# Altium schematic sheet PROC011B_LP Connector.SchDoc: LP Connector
size 431 x 279 mm; Date: Not shown in title block; ApprovedBy: Not shown in title block; CheckedBy: Not shown in title block; Author: Not shown in title block; CompanyName: Not shown in title block; Engineer: Not shown in title block; Organization: Not shown in title block; Address1: Not shown in title block; Address2: Not shown in title block; Address3: Not shown in title block; Address4: Not shown in title block; DocumentNumber: 1; Revision: Use project parameter SCH_Rev; SheetNumber: 10; SheetTotal: 17; PageSetup: Record=PageOptions¦CenterHorizontal=True¦CenterVertical=True¦PrintScale=1.00¦XCorrection=1.00¦YCorrection=1.00¦PrintKind=0¦BorderSize=5000000¦LeftOffset=0¦BottomOffset=0¦Orientation=2¦PaperLength=1000¦PaperWidth=1000¦Scale=100¦PaperSource=15¦PrintQuality=600¦MediaType=1¦DitherType=10¦PaperKind=Letter¦PrintScaleMode=1
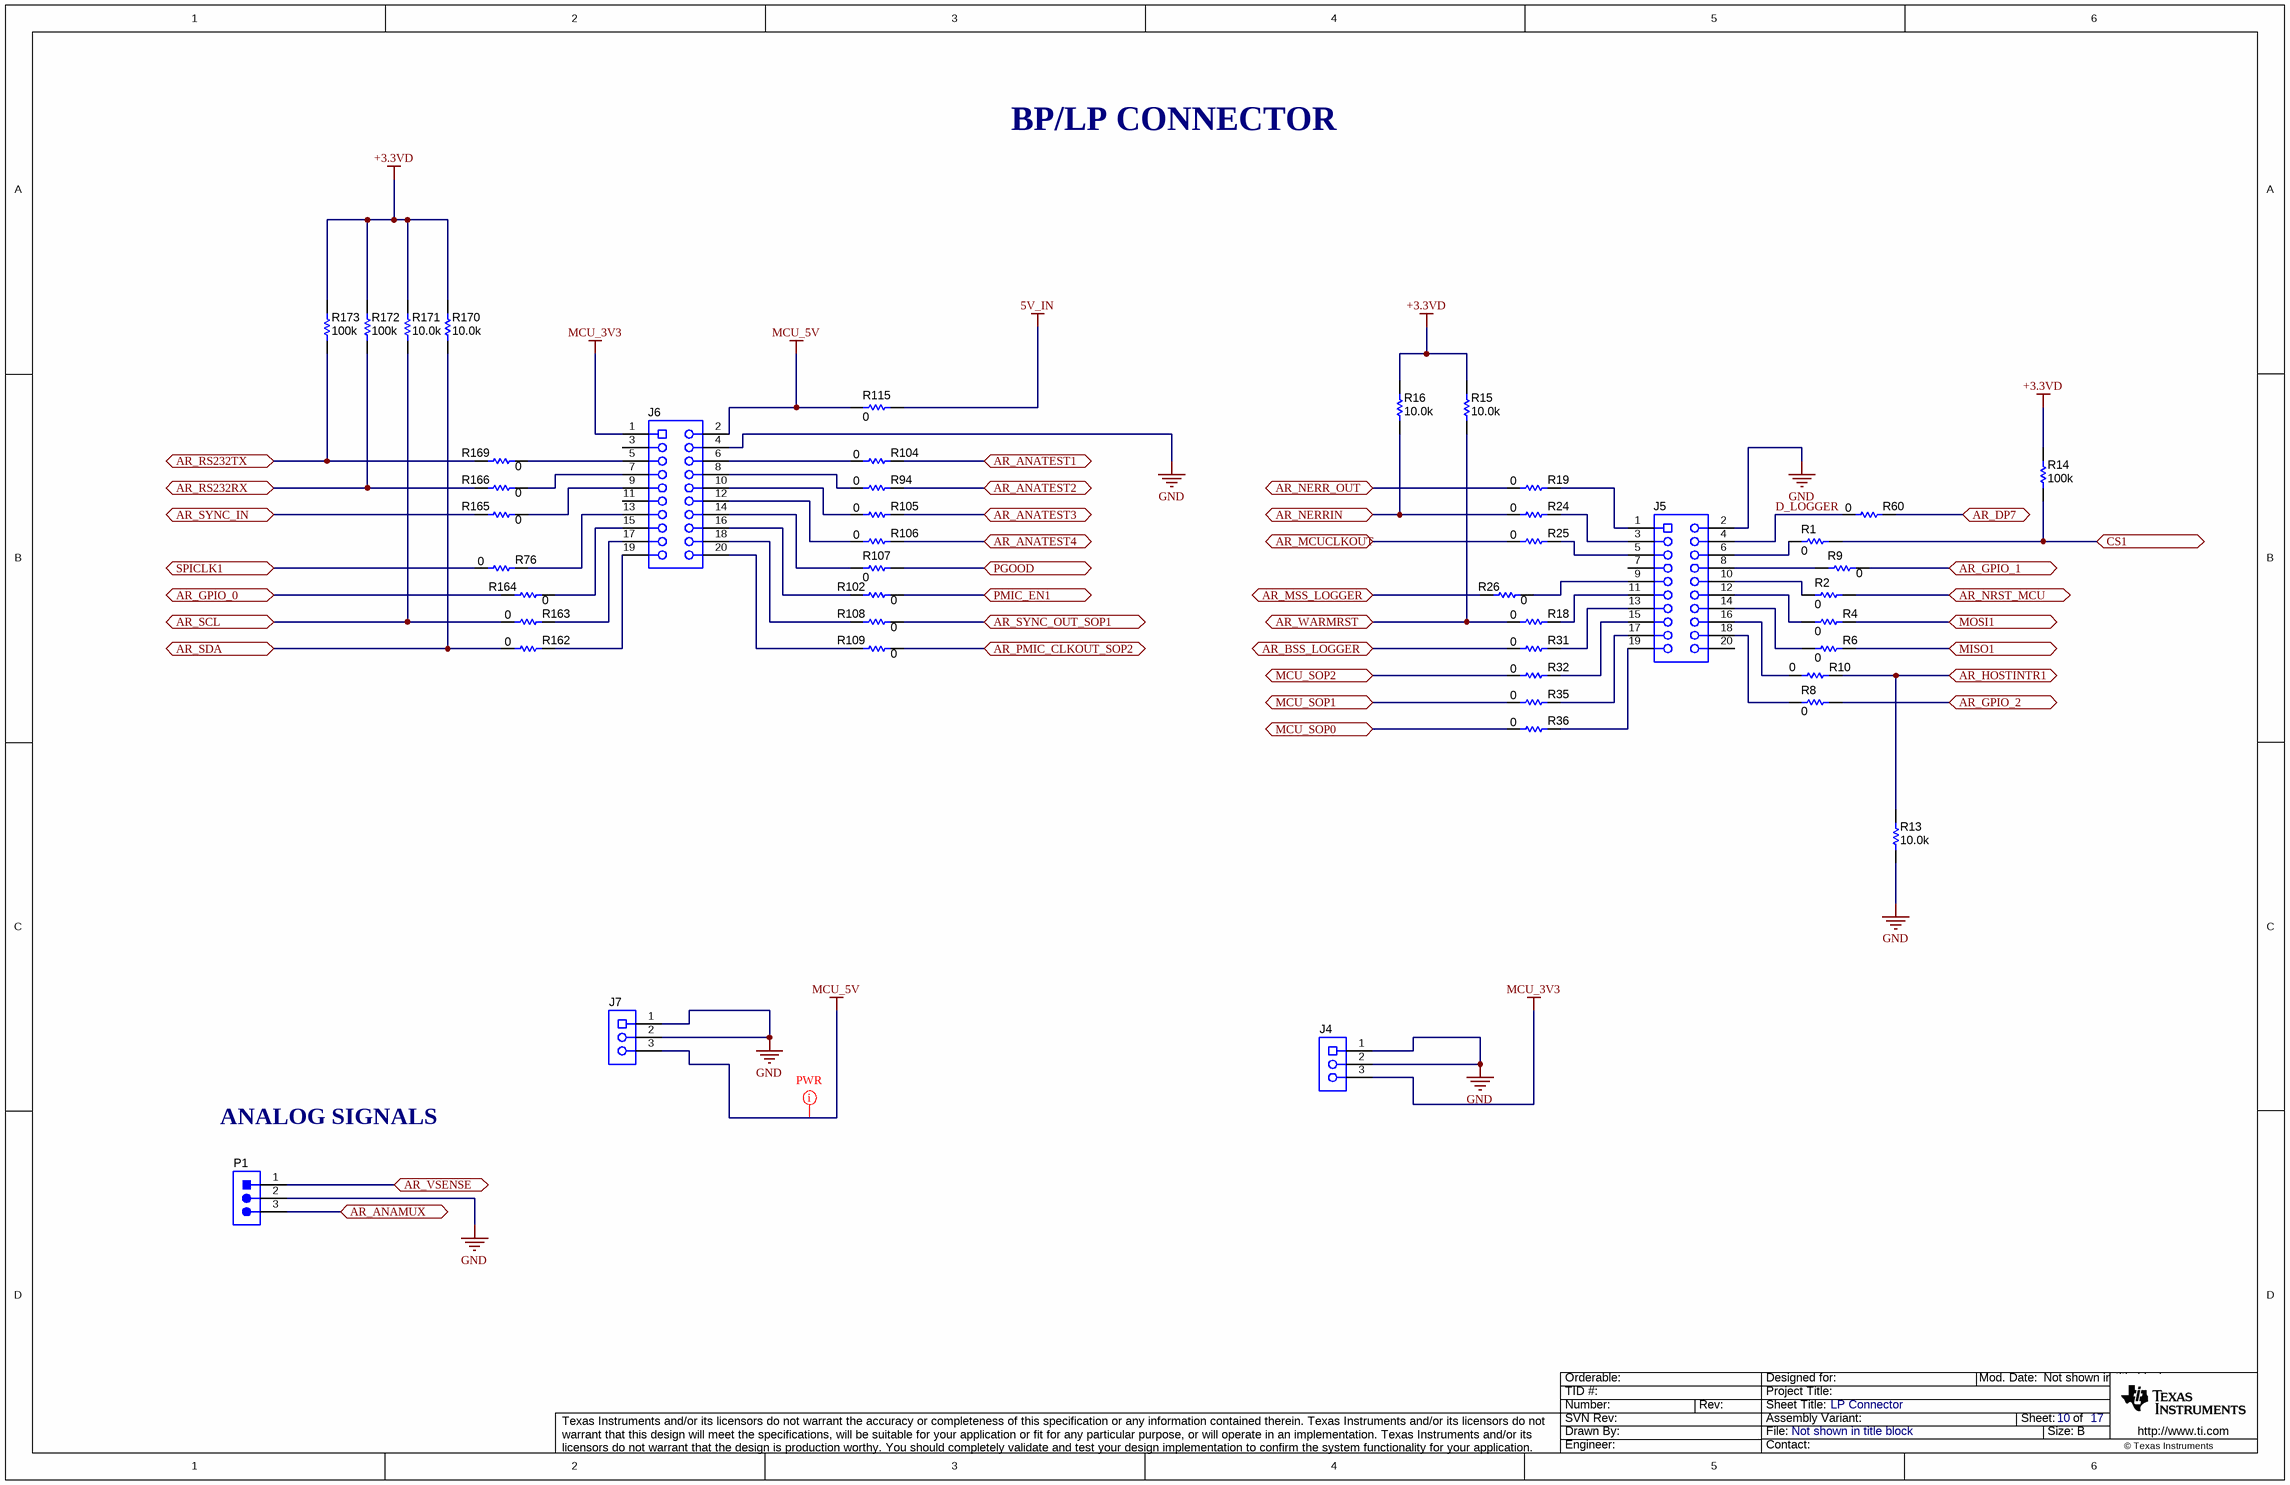
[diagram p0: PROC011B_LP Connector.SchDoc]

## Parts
J4  SSM-103-S-SV  [Samtec_SSM-103-x-SV]  (value not drawn)
J5  SSM-110-S-DV  [Samtec_SSM-110-x-DV]  (value not drawn)
J6  SSM-110-S-DV  [Samtec_SSM-110-x-DV]  (value not drawn)
J7  SSM-103-S-SV  [Samtec_SSM-103-x-SV]  (value not drawn)
P1  TSW-103-07-T-S  [Samtec_TSW-103-07-T-S]  (value not drawn)
R1  ValueDisplayed: 0  [0201_Silk]  (hidden comment: CRCW02010000Z0ED)
R2  ValueDisplayed: 0  [0201_Silk]  (hidden comment: CRCW02010000Z0ED)
R4  ValueDisplayed: 0  [0201_Silk]  (hidden comment: CRCW02010000Z0ED)
R6  ValueDisplayed: 0  [0201_Silk]  (hidden comment: CRCW02010000Z0ED)
R8  ValueDisplayed: 0  [0201_Silk]  (hidden comment: CRCW02010000Z0ED)
R9  ValueDisplayed: 0  [0201_Silk]  (hidden comment: CRCW02010000Z0ED)
R10  ValueDisplayed: 0  [0201_Silk]  (hidden comment: CRCW02010000Z0ED)
R13  ValueDisplayed: 10.0k  [0402L]  (hidden comment: CRCW040210K0FKED)
R14  ValueDisplayed: 100k  [0402L]  (hidden comment: CRCW0402100KFKED)
R15  ValueDisplayed: 10.0k  [0402L]  (hidden comment: CRCW040210K0FKED)
R16  ValueDisplayed: 10.0k  [0402L]  (hidden comment: CRCW040210K0FKED)
R18  ValueDisplayed: 0  [0201_Silk]  (hidden comment: CRCW02010000Z0ED)
R19  ValueDisplayed: 0  [0201_Silk]  (hidden comment: CRCW02010000Z0ED)
R24  ValueDisplayed: 0  [0201_Silk]  (hidden comment: CRCW02010000Z0ED)
R25  ValueDisplayed: 0  [0201_Silk]  (hidden comment: CRCW02010000Z0ED)
R26  ValueDisplayed: 0  [0201_Silk]  (hidden comment: CRCW02010000Z0ED)
R31  ValueDisplayed: 0  [0201_Silk]  (hidden comment: CRCW02010000Z0ED)
R32  ValueDisplayed: 0  [0201_Silk]  (hidden comment: CRCW02010000Z0ED)
R35  ValueDisplayed: 0  [0201_Silk]  (hidden comment: CRCW02010000Z0ED)
R36  ValueDisplayed: 0  [0201_Silk]  (hidden comment: CRCW02010000Z0ED)
R60  ValueDisplayed: 0  [0201_Silk]  (hidden comment: CRCW02010000Z0ED)
R76  ValueDisplayed: 0  [0201_Silk]  (hidden comment: CRCW02010000Z0ED)
R94  ValueDisplayed: 0  [0201_Silk]  (hidden comment: CRCW02010000Z0ED)
R102  ValueDisplayed: 0  [0201_Silk]  (hidden comment: CRCW02010000Z0ED)
R104  ValueDisplayed: 0  [0201_Silk]  (hidden comment: CRCW02010000Z0ED)
R105  ValueDisplayed: 0  [0201_Silk]  (hidden comment: CRCW02010000Z0ED)
R106  ValueDisplayed: 0  [0201_Silk]  (hidden comment: CRCW02010000Z0ED)
R107  ValueDisplayed: 0  [0402L]  (hidden comment: ERJ-2GE0R00X)
R108  ValueDisplayed: 0  [0201_Silk]  (hidden comment: CRCW02010000Z0ED)
R109  ValueDisplayed: 0  [0201_Silk]  (hidden comment: CRCW02010000Z0ED)
R115  ValueDisplayed: 0  [2010]  (hidden comment: CRCW20100000Z0EF)
R162  ValueDisplayed: 0  [0201_Silk]  (hidden comment: CRCW02010000Z0ED)
R163  ValueDisplayed: 0  [0201_Silk]  (hidden comment: CRCW02010000Z0ED)
R164  ValueDisplayed: 0  [0201_Silk]  (hidden comment: CRCW02010000Z0ED)
R165  ValueDisplayed: 0  [0201_Silk]  (hidden comment: CRCW02010000Z0ED)
R166  ValueDisplayed: 0  [0201_Silk]  (hidden comment: CRCW02010000Z0ED)
R169  ValueDisplayed: 0  [0201_Silk]  (hidden comment: CRCW02010000Z0ED)
R170  ValueDisplayed: 10.0k  [0402L]  (hidden comment: CRCW040210K0FKED)
R171  ValueDisplayed: 10.0k  [0402L]  (hidden comment: CRCW040210K0FKED)
R172  ValueDisplayed: 100k  [0402L]  (hidden comment: CRCW0402100KFKED)
R173  ValueDisplayed: 100k  [0402L]  (hidden comment: CRCW0402100KFKED)

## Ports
AR_ANAMUX, AR_ANATEST1, AR_ANATEST2, AR_ANATEST3, AR_ANATEST4, AR_BSS_LOGGER, AR_DP7, AR_GPIO_0, AR_GPIO_1, AR_GPIO_2, AR_HOSTINTR1, AR_MCUCLKOUT, AR_MSS_LOGGER, AR_NERR_OUT, AR_NERRIN, AR_NRST_MCU, AR_PMIC_CLKOUT_SOP2, AR_RS232RX, AR_RS232TX, AR_SCL, AR_SDA, AR_SYNC_IN, AR_SYNC_OUT_SOP1, AR_VSENSE, AR_WARMRST, CS1, MCU_SOP0, MCU_SOP1, MCU_SOP2, MISO1, MOSI1, PGOOD, PMIC_EN1, SPICLK1

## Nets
5V_IN: R115.2
+3.3VD: R14.2 R15.2 R16.2 R170.2 R171.2 R172.2 R173.2
GND: J4.1 J4.2 J5.2 J6.4 J7.1 J7.2 P1.2 R13.1
MCU_3V3: J4.3 J6.1
MCU_5V: J6.2 J7.3 R115.1
AR_ANAMUX: P1.3 ; port AR_ANAMUX
AR_ANATEST1: R104.2 ; port AR_ANATEST1
AR_ANATEST2: R94.2 ; port AR_ANATEST2
AR_ANATEST3: R105.2 ; port AR_ANATEST3
AR_ANATEST4: R106.2 ; port AR_ANATEST4
AR_BSS_LOGGER: R31.1 ; port AR_BSS_LOGGER
AR_DP7: R60.2 ; port AR_DP7
AR_GPIO_0: R164.1 ; port AR_GPIO_0
AR_GPIO_1: R9.2 ; port AR_GPIO_1
AR_GPIO_2: R8.2 ; port AR_GPIO_2
AR_HOSTINTR1: R10.2 R13.2 ; port AR_HOSTINTR1
AR_MCUCLKOUT: R25.1 ; port AR_MCUCLKOUT
AR_MSS_LOGGER: R26.1 ; port AR_MSS_LOGGER
AR_NERR_OUT: R19.1 ; port AR_NERR_OUT
AR_NERRIN: R16.1 R24.1 ; port AR_NERRIN
AR_NRST_MCU: R2.2 ; port AR_NRST_MCU
AR_PMIC_CLKOUT_SOP2: R109.2 ; port AR_PMIC_CLKOUT_SOP2
AR_RS232RX: R166.1 R172.1 ; port AR_RS232RX
AR_RS232TX: R169.1 R173.1 ; port AR_RS232TX
AR_SCL: R163.1 R171.1 ; port AR_SCL
AR_SDA: R162.1 R170.1 ; port AR_SDA
AR_SYNC_IN: R165.1 ; port AR_SYNC_IN
AR_SYNC_OUT_SOP1: R108.2 ; port AR_SYNC_OUT_SOP1
AR_VSENSE: P1.1 ; port AR_VSENSE
AR_WARMRST: R15.1 R18.1 ; port AR_WARMRST
CS1: R1.2 R14.1 ; port CS1
D_LOGGER: J5.4 R60.1
MCU_SOP0: R36.1 ; port MCU_SOP0
MCU_SOP1: R35.1 ; port MCU_SOP1
MCU_SOP2: R32.1 ; port MCU_SOP2
MISO1: R6.2 ; port MISO1
MOSI1: R4.2 ; port MOSI1
PGOOD: R107.2 ; port PGOOD
PMIC_EN1: R102.2 ; port PMIC_EN1
SPICLK1: R76.1 ; port SPICLK1
NetJ5_1: J5.1 R19.2
NetJ5_3: J5.3 R24.2
NetJ5_5: J5.5 R25.2
NetJ5_6: J5.6 R1.1
NetJ5_8: J5.8 R9.1
NetJ5_9: J5.9 R26.2
NetJ5_10: J5.10 R2.1
NetJ5_11: J5.11 R18.2
NetJ5_12: J5.12 R4.1
NetJ5_13: J5.13 R31.2
NetJ5_14: J5.14 R6.1
NetJ5_15: J5.15 R32.2
NetJ5_16: J5.16 R10.1
NetJ5_17: J5.17 R35.2
NetJ5_18: J5.18 R8.1
NetJ5_19: J5.19 R36.2
NetJ6_5: J6.5 R169.2
NetJ6_6: J6.6 R104.1
NetJ6_7: J6.7 R166.2
NetJ6_8: J6.8 R94.1
NetJ6_9: J6.9 R165.2
NetJ6_10: J6.10 R105.1
NetJ6_12: J6.12 R106.1
NetJ6_13: J6.13 R76.2
NetJ6_14: J6.14 R107.1
NetJ6_15: J6.15 R164.2
NetJ6_16: J6.16 R102.1
NetJ6_17: J6.17 R163.2
NetJ6_18: J6.18 R108.1
NetJ6_19: J6.19 R162.2
NetJ6_20: J6.20 R109.1

Not connected (* = marked no-connect by the designer): J5 7 20; J6 3 11

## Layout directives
net class PWR: MCU_5V

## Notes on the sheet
- BP/LP CONNECTOR
- ANALOG SIGNALS

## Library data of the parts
J4 J7 = CMP-0078183-1: Receptacle, 2.54mm, 3x1, Gold with Tin tail, SMT; Manufacturer: Samtec; Pitch_mm: 2.54; Gender: Female; Cert_CSA: Y; Voltage_V: 405V; Current_A: 5.2A; Row_Count: 1; CompType: Socket Strip
J5 J6 = CMP-0078182-1: Receptacle, 2.54mm, 10x2, Gold with Tin tail, SMT; Manufacturer: Samtec; Pitch_mm: 2.54; Gender: Female; Cert_CSA: Y; Voltage_V: 405V; Current_A: 5.2A; Row_Count: 2; CompType: Socket Strip
P1 = CMP-0075530-1: Header, 2.54 mm, 3x1, Tin, TH; Manufacturer: Samtec; Pitch_mm: 2.54; Cert_VDE: N; Gender: Male; Cert_CSA: Y; Voltage_V: 550V; Green_REACh: Passed; Current_A: 6.3A; CT: False; Green_Lifecycle: Active; Row_Count: 1; CNHeader: True
R1 R2 R18 R19 R24 R25 R31 R32 R35 R36 R76 R94 R104-R106 R162 R163 = CMP-0027008-3: RES, 0, 5%, 0.05 W, 0201; Manufacturer: Vishay-Dale; Power_W: 50mW; TempCo: ppm/C; Value_Code: 0000; U/M: EA; Value: 0; EIA_Code: E24; SizeX_mm: 0.6; SizeY_mm: 0.3; SizeZ_mm: 0.26; Value2: 0.05W; SizeArea_mm2: 0.18; AEC Qualified: N; AEC Category: Q200
R4 R6 R10 R60 = CMP-0027008-3: RES, 0, 5%, 0.05 W, 0201; Manufacturer: Vishay-Dale; Power_W: 50mW; TempCo: ppm/C; Value_Code: 0000; U/M: EA; Value: 0; EIA_Code: E24; SizeX_mm: 0.6; SizeY_mm: 0.3; SizeZ_mm: 0.26; Value2: 0.05W; SizeArea_mm2: 0.18; CompType: Resistor; AEC Qualified: N; AEC Category: Q200
R8 R9 R26 R102 R108 R109 R164-R166 R169 = CMP-0027008-3: RES, 0, 5%, 0.05 W, 0201; Manufacturer: Vishay-Dale; Power_W: 50mW; TempCo: ppm/C; Value_Code: 0000; U/M: EA; Value: 0; EIA_Code: E24; SizeX_mm: 0.6; SizeY_mm: 0.3; SizeZ_mm: 0.26; Value2: 0.05W; SizeArea_mm2: 0.18; CompType: Resistor; AEC Qualified: N; AEC Category: Q200; INSTALATION: DNP
R13 R15 R16 R170 R171 = CMP-0025958-2: RES, 10.0 k, 1%, 0.063 W, 0402; Manufacturer: Vishay-Dale; Power_W: 63mW; TempCo: 100 ppm/C; Value_Code: 10k0; U/M: EA; Value: 10.0k; EIA_Code: E96; Res_ohm: 10k; SizeX_mm: 1; SizeY_mm: 0.5; SizeZ_mm: 0.6; Value2: 0.063W; VDC_V: 50V; AEC Category: Q200
R14 R172 R173 = CMP-0025950-2: RES, 100 k, 1%, 0.063 W, 0402; Manufacturer: Vishay-Dale; Power_W: 63mW; TempCo: 100 ppm/C; U/M: EA; Value: 100k; EIA_Code: E96; SizeX_mm: 1; SizeY_mm: 0.5; SizeZ_mm: 0.6; Value2: 0.063W; VDC_V: 50V; AEC Category: Q200
R107 = CMP-0026992-2: RES, 0, 5%, 0.063 W, 0402; Manufacturer: Panasonic; Power_W: 63mW; TempCo: 600 ppm/C; Value_Code: 0000; U/M: EA; Value: 0; EIA_Code: E24; SizeX_mm: 1; SizeY_mm: 0.5; SizeZ_mm: 0.6; Value2: 0.063W; VDC_V: 50V; AEC Category: Q200
R115 = CMP-0016044-2: RES, 0, 5%, 0.75 W, AEC-Q200 Grade 0, 2010; Manufacturer: Vishay-Dale; Power_W: 750mW; TempCo: ppm/C; Value_Code: 0000; U/M: EA; Value: 0; EIA_Code: E24; SizeX_mm: 5; SizeY_mm: 2.5; SizeZ_mm: 1.66; Value2: 0.75W; SizeArea_mm2: 12.5; CompType: Resistor; AEC Qualified: Y; AEC Category: Q200; INSTALATION: DNP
